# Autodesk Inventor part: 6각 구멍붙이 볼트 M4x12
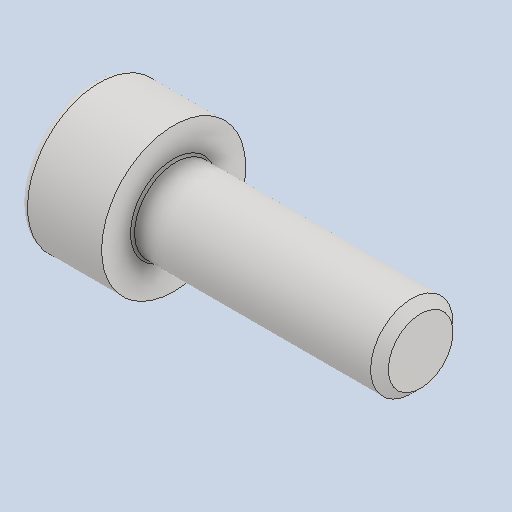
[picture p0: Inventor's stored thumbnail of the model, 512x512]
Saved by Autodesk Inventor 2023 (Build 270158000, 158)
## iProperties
Created: 2025-03
Part Number: 6각 구멍붙이 볼트 M4x12
Material: 스테인리스강
Description: 6각 소켓 머리 캡 나사
Document SubType Name: Modeling
Designer: User
Density: 8.08 g/cm^3
Appearance: 기본값
Author: jhkim
Sending System: Autodesk Inventor 2025
Preprocessor: ST-DEVELOPER v20
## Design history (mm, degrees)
feature "Solid1"
node "솔리드1"
